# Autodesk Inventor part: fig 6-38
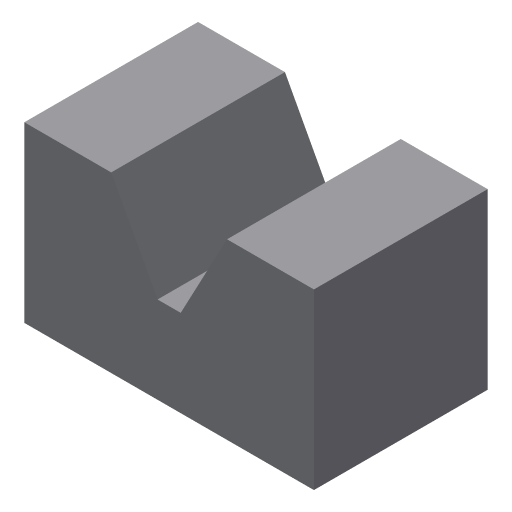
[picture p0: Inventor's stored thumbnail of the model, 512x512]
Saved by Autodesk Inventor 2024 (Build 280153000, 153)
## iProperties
Created: 2005-12
Part Number: fig 6-38
Document SubType Name: Modeling
Designer: CADCIM
Density: 1 g/cm^3
Material: Generic
Appearance: Default
Author: CADCIM
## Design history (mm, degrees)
sketch "Sketch1"
  geometry: L1 (10, 15)-(25, 15); L2 (25, 15)-(25, -15); L3 (25, -15)-(-25, -15); L4 (-25, -15)-(-25, 15); L5 (-25, 15)-(-10, 15); L6 (-10, 15)-(-2, 0); L7 (-2, 0)-(2, 0); L8 (2, 0)-(10, 15); 1 further point
  constraints: 16 end point, 3 equal length, 3 parallel, 1 collinear, 1 horizontal, 1 perpendicular, 1 other
  dimensions: "d0" = 50 distance of L2.end L3.end; "d1" = 25 distance from line of point (0, 0) L2; "d2" = 30 distance of L1.end L2.end; "d3" = 15 distance of L1.start L1.end; "d4" = 15 distance between parallel lines of L1 L7; "d5" = 4 distance of L6.end L7.end; "d6" = 15 distance from line of point (0, 0) L3
extrude "Extrusion1" new body sketch "Sketch1" stored distance "d7" = 30; taper "d8" = 0 deg
body "Solid1"
